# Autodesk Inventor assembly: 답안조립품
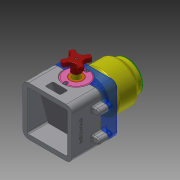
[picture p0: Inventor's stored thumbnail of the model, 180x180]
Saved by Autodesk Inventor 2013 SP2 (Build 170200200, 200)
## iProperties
Created: 2022-03
Part Number: 답안조립품
Document SubType Name: Assembly
Designer: i
Author: i
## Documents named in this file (11)
- C:\Users\i\Desktop\배승현\720306V1024\답안조립품.iam
- C:\Users\i\Desktop\배승현\720306V1024\본체.ipt
- C:\Users\i\Desktop\배승현\720306V1024\본체커버.ipt
- C:\Users\i\Desktop\배승현\720306V1024\용기.ipt
- C:\Users\i\Desktop\배승현\720306V1024\앞커버.ipt
- C:\Users\i\Desktop\배승현\720306V1024\핸들.ipt
- C:\Users\i\Desktop\배승현\720306V1024\핸들축.ipt
- C:\Users\i\Desktop\배승현\720306V1024\볼트 M4x12.ipt
- C:\Users\i\Desktop\배승현\720306V1024\용기캡.ipt
- C:\Users\i\Desktop\배승현\720306V1024\볼트 M3x12.ipt
- C:\Users\i\Desktop\배승현\720306V1024\베어링 부시.ipt
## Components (2 placed, 2 different names)
1. 핸들:1
2. 핸들축:1
